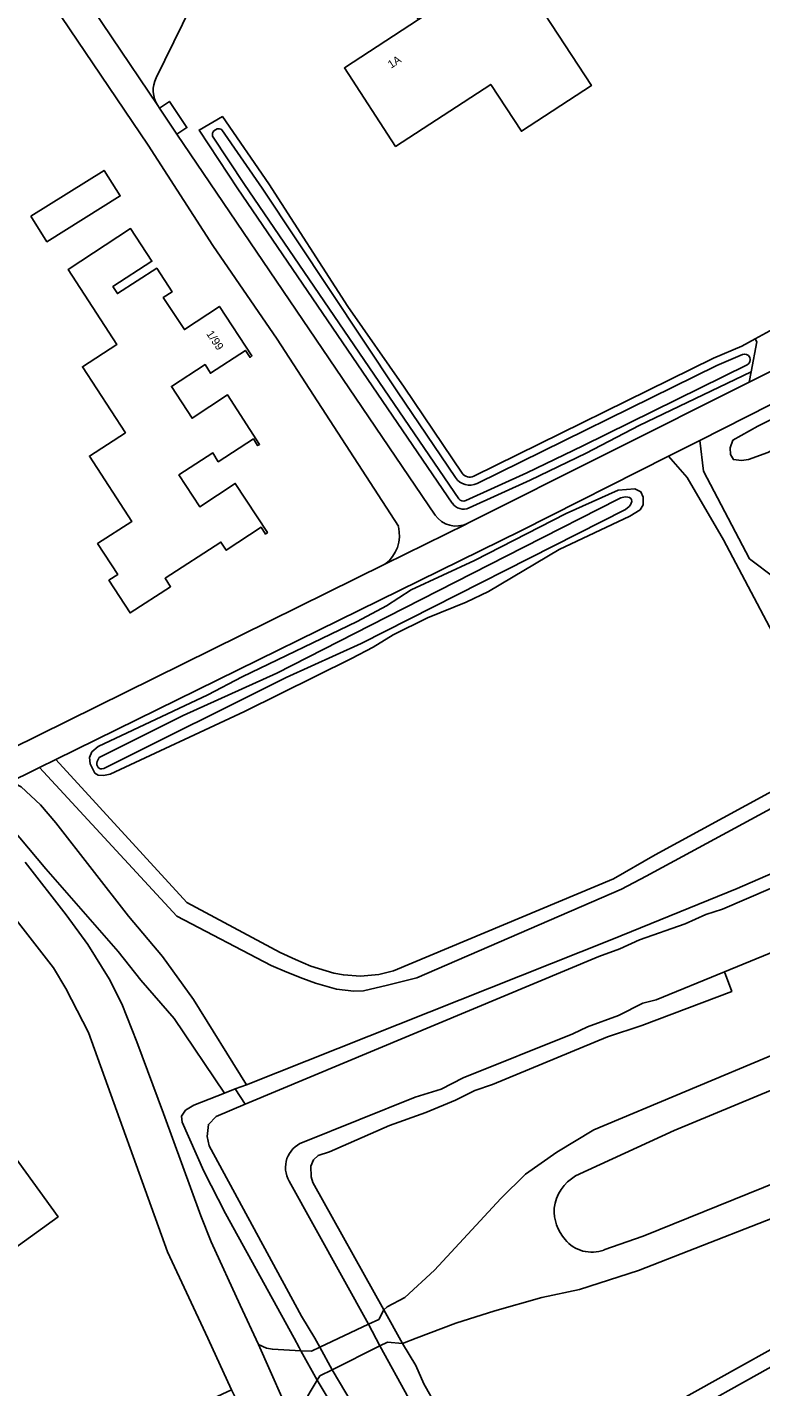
# Model space of a CAD drawing. Extents: x 162788 to 163838, y 385791 to 386523.
# Drawn here: x 163143.1 to 163234.7, y 386243.9 to 386413.8 of the extents above; entities that cross this region are included whole.
import ezdxf

# ---------------------------------------------------------------- set-up
doc = ezdxf.new("R2010")
doc.units = 0
for name, color, linetype in [('IMGEO_Dek', 7, 'Continuous'), ('IMGEO_Duiker', 7, 'Continuous'), ('IMGEO_Erf', 7, 'Continuous'), ('IMGEO_Gemengd_bos', 7, 'Continuous'), ('IMGEO_Groenvoorziening', 7, 'Continuous'), ('IMGEO_Oever', 7, 'Continuous'), ('IMGEO_Pand', 7, 'Continuous'), ('IMGEO_Pand_nummerreeks', 7, 'Continuous'), ('IMGEO_Pand_vergunning_verleend', 7, 'Continuous'), ('IMGEO_Rijbaan_lokaal_gesloten', 7, 'Continuous'), ('IMGEO_Voetpad_halfverhard', 7, 'Continuous'), ('IMGEO_Voetpad_open', 7, 'Continuous'), ('IMGEO_Waterloop', 7, 'Continuous'), ('IMGEO_Woonerf_open', 7, 'Continuous')]:
    doc.layers.add(name, color=color, linetype=linetype)

msp = doc.modelspace()

# ---------------------------------------------------------------- linework, layer by layer
at = {"layer": 'IMGEO_Dek'}
msp.add_lwpolyline([(163187.14, 386249.05), (163188.1, 386249.52), (163189.98, 386249.35), (163187.66, 386253.56), (163187.03, 386252.37), (163185.76, 386251.76), (163179.68, 386248.88), (163178.62, 386248.38), (163177.3, 386248.45), (163179.35, 386244.77), (163179.68, 386245.3), (163181.21, 386246.07)], close=True, dxfattribs=at)
at = {"layer": 'IMGEO_Duiker'}
msp.add_lwpolyline([(163170.35, 386279.25), (163169.11, 386281.15)], dxfattribs=at)
at = {"layer": 'IMGEO_Erf'}
for points in [[(163183.82, 386453.68), (163203.35, 386423.5), (163202.72, 386423.13), (163213.57, 386406.51), (163204.83, 386400.81), (163201, 386406.67), (163189.13, 386398.92), (163182.73, 386408.73), (163191.99, 386414.77), (163181.96, 386429.74), (163190.95, 386435.96), (163184.59, 386445.9)], [(163176.85, 386443.41), (163159.22, 386407.47)], [(163189.47, 386351.45), (163174.34, 386374.85), (163166.31, 386386.55), (163158.23, 386399.07), (163142.49, 386422.41)], [(163198.88, 386357.71), (163228.84, 386372.45), (163232.38, 386373.97), (163234.01, 386374.89), (163236.33, 386376.13), (163247.03, 386381.44), (163261.91, 386388.47), (163285.34, 386400.29), (163291.96, 386403.48), (163304.5, 386410.04)], [(163159.42, 386404.03), (163159.64, 386403.68), (163160.87, 386404.53), (163163.06, 386401.27), (163161.79, 386400.43), (163194.06, 386352.86)], [(163196.21, 386354.34), (163169.41, 386393.61), (163164.58, 386400.96), (163167.5, 386402.64), (163173.28, 386394.26), (163183.14, 386378.9), (163190.19, 386368.84), (163197.45, 386358.09)], [(163198.08, 386351.82), (163233.27, 386369.45), (163233.53, 386370.77), (163219.54, 386364.04), (163212.94, 386360.6), (163205.94, 386357.23), (163198.3, 386353.75)], [(163091.31, 386354.73), (163115.97, 386329.92), (163121.7, 386323.72), (163123.09, 386322.59), (163126.27, 386320.63), (163127.78, 386320.01), (163129.72, 386319.21), (163129.91, 386319.12), (163130.11, 386319.04), (163130.32, 386318.97), (163130.52, 386318.93), (163130.74, 386318.9), (163130.95, 386318.89), (163131.17, 386318.9), (163131.38, 386318.93), (163131.59, 386318.97), (163131.8, 386319.04), (163132, 386319.12), (163132.19, 386319.21), (163137.37, 386321.83), (163187.8, 386346.71)], [(163202.05, 386229.7), (163238.52, 386250), (163263.57, 386263.94), (163278.14, 386271.64), (163288.89, 386277.59), (163289.29, 386277.99), (163289.57, 386278.55), (163289.29, 386279.83), (163285.21, 386290.76), (163283.84, 386294.94), (163285.26, 386295.57), (163284.13, 386298.22), (163282.71, 386297.57), (163282.08, 386299.04), (163280.52, 386303.16), (163279.76, 386304.64), (163276.83, 386311.46)], [(163130.61, 386225.91), (163168.65, 386243.58), (163165.66, 386250), (163160.64, 386260.8), (163150.79, 386288.19), (163147.95, 386293.69), (163146.39, 386296.27), (163137.48, 386307.69)], [(163252.5, 386304.93), (163230.21, 386295.8), (163231.11, 386293.35), (163219.88, 386289.08), (163215.6, 386287.65), (163201.22, 386281.72), (163199.02, 386280.98), (163196.61, 386279.76), (163192.89, 386278.2), (163188.38, 386276.6), (163180.89, 386273.3), (163179.47, 386272.86), (163178.89, 386272.28), (163178.54, 386271.49), (163178.59, 386270.16), (163178.79, 386269.46), (163187.66, 386253.56), (163188.07, 386253.92), (163190.27, 386255.1), (163193.97, 386258.51), (163202.25, 386267.46), (163205.34, 386270.51), (163209.26, 386273.27), (163213.9, 386276.05), (163236.95, 386285.72)], [(163139.77, 386275.14), (163146.97, 386265.18), (163119.61, 386245.38)], [(163242.46, 386267.47), (163219.47, 386258.48), (163212.11, 386256.1), (163207.4, 386255.09), (163201.52, 386253.45), (163196.64, 386251.88), (163191.7, 386250), (163189.98, 386249.35), (163191.66, 386246.6), (163192.64, 386244.3), (163200.49, 386230.52)]]:
    msp.add_lwpolyline(points, dxfattribs=at)
msp.add_lwpolyline([(163151.91, 386349.29), (163156.19, 386352.07), (163150.89, 386360.23), (163155.38, 386363.14), (163150.02, 386371.39), (163154.3, 386374.16), (163148.22, 386383.52), (163156.04, 386388.64), (163158.69, 386384.56), (163153.82, 386381.4), (163154.38, 386380.52), (163159.29, 386383.69), (163161.21, 386380.74), (163160.11, 386380.03), (163162.75, 386376.04), (163167.13, 386378.92), (163171.18, 386372.74), (163170.95, 386372.55), (163170.37, 386373.43), (163166.01, 386370.57), (163165.33, 386371.66), (163161.12, 386368.93), (163163.7, 386364.96), (163168.14, 386367.86), (163172.15, 386361.69), (163171.9, 386361.54), (163171.36, 386362.38), (163166.98, 386359.52), (163166.31, 386360.63), (163162.07, 386357.88), (163164.66, 386353.89), (163169.1, 386356.82), (163173.12, 386350.66), (163172.89, 386350.49), (163172.32, 386351.34), (163167.97, 386348.46), (163167.31, 386349.49), (163160.34, 386344.96), (163161.02, 386343.91), (163155.97, 386340.63), (163153.32, 386344.72), (163154.42, 386345.44)], close=True, dxfattribs=at)
for centre, radius, start, end in [((163162.36, 386405.93), 3.5, 153.8321, 212.7602), ((163198.38, 386358.72), 1.13, 213.9935, 296.382), ((163197.6, 386355.28), 1.68, 214.2495, 294.4272), ((163185.11, 386350.32), 4.5, 306.6921, 14.4455), ((163196.67, 386354.64), 3.16, 214.3208, 296.6637)]:
    msp.add_arc(centre, radius, start, end, dxfattribs=at)
at = {"layer": 'IMGEO_Gemengd_bos'}
for points in [[(163251.31, 386374.37), (163244.77, 386371.12), (163227.11, 386362.18), (163227.57, 386358.35), (163233.34, 386347.39), (163236.53, 386344.99), (163240.87, 386344.48), (163246.3, 386346.08), (163265.57, 386354.14), (163258.98, 386369.88)], [(163249.73, 386367.6), (163239.39, 386362.73), (163235.63, 386360.67), (163233.19, 386359.79), (163232.32, 386359.69), (163231.31, 386359.79), (163230.93, 386360.43), (163230.89, 386361.27), (163231.25, 386362.21), (163234.35, 386363.97), (163242.51, 386368), (163251.65, 386372.2), (163251.93, 386372.33)], [(163245.56, 386321.36), (163220.43, 386307.74), (163217.35, 386306.13), (163191.76, 386295.05), (163188.1, 386294.14), (163185.1, 386293.41), (163183.89, 386293.36), (163181.73, 386293.63), (163179.14, 386294.37), (163177.56, 386294.94), (163175.56, 386295.74), (163173.59, 386296.58), (163161.79, 386302.75), (163144.67, 386321.31), (163140.19, 386319.11)], [(163142.36, 386318.89), (163144.8, 386316.64), (163146.68, 386314.42), (163155.79, 386302.74), (163160.03, 386297.72), (163163.89, 386292.32), (163170.49, 386281.68), (163216.12, 386299.84), (163231.77, 386306.19), (163236.27, 386308.14)], [(163142.88, 386309.51), (163148, 386302.92), (163150.68, 386299.19), (163153.35, 386294.91), (163154.95, 386291.78), (163156.81, 386287.04), (163160.14, 386278.08), (163164.81, 386265.29), (163166.11, 386262.07), (163169.72, 386254.16), (163171.99, 386249.22), (163173.01, 386248.79), (163173.75, 386248.64), (163177.3, 386248.45), (163177.07, 386248.86), (163176.45, 386250), (163167.9, 386265.59), (163165.18, 386270.87), (163162.48, 386277.01), (163162.4, 386277.75), (163162.9, 386278.49), (163163.94, 386279.15), (163167.75, 386280.62), (163161.49, 386289.96), (163157.29, 386294.73), (163154.47, 386298.31), (163145.44, 386308.65), (163140.02, 386315.11)]]:
    msp.add_lwpolyline(points, dxfattribs=at)
for points in [[(163223.2, 386360.2), (163204.76, 386350.87), (163146.68, 386322.3), (163163.05, 386304.46), (163174.71, 386298.21), (163176.62, 386297.32), (163178.56, 386296.51), (163181.4, 386295.62), (163182.61, 386295.4), (163184.73, 386295.24), (163187.04, 386295.46), (163188.87, 386295.91), (163216.32, 386307.39), (163221.54, 386310.39), (163244.17, 386322.73), (163244.86, 386324.42), (163239.28, 386332.37), (163230.09, 386349.78), (163225.52, 386357.53)], [(163209.54, 386348.55), (163200.74, 386343.3), (163197.94, 386341.96), (163193.12, 386340.02), (163188.82, 386337.91), (163186.33, 386336.35), (163183.63, 386334.93), (163170.27, 386328.3), (163153.46, 386320.5), (163152.64, 386320.3), (163151.98, 386320.36), (163151.58, 386320.62), (163151, 386321.78), (163150.92, 386322.58), (163151.2, 386323.26), (163151.98, 386323.94), (163165.69, 386330.39), (163169.95, 386332.64), (163184.33, 386339.55), (163188.01, 386341.51), (163191.08, 386343.52), (163198.98, 386347.2), (163210.42, 386353.07), (163216.94, 386355.98), (163219.02, 386356.12), (163219.76, 386355.76), (163220.05, 386355.08), (163220.04, 386354.14), (163219.65, 386353.5), (163218.39, 386352.7)]]:
    msp.add_lwpolyline(points, close=True, dxfattribs=at)
at = {"layer": 'IMGEO_Groenvoorziening'}
for points in [[(163238.51, 386281.93), (163236.46, 386281.19), (163223.91, 386275.96), (163211.61, 386270.29)], [(163215.15, 386261.04), (163220.05, 386262.77), (163240.72, 386271.13)], [(163182.41, 386239.63), (163179.69, 386244.16), (163179.35, 386244.77), (163178.47, 386243.33)]]:
    msp.add_lwpolyline(points, dxfattribs=at)
for centre, radius, start, end in [((163214.22, 386265.65), 5.32, 119.4185, 173.4513), ((163214.33, 386265.94), 5.4, 176.5722, 221.7042), ((163213.64, 386265.1), 4.34, 219.5286, 290.4148)]:
    msp.add_arc(centre, radius, start, end, dxfattribs=at)
at = {"layer": 'IMGEO_Oever'}
for points in [[(163197.45, 386358.09), (163190.19, 386368.84), (163183.14, 386378.9), (163173.28, 386394.26), (163167.5, 386402.64), (163164.58, 386400.96), (163169.41, 386393.61), (163196.21, 386354.34)], [(163166.44, 386400.88), (163166.84, 386401.11)], [(163167.43, 386400.97), (163172.45, 386393.71), (163189.37, 386368.27), (163196.62, 386357.53)], [(163197.04, 386354.9), (163170.24, 386394.17), (163166.28, 386400.2)], [(163198.3, 386353.75), (163205.94, 386357.23), (163212.94, 386360.6), (163219.54, 386364.04), (163233.53, 386370.77), (163234.25, 386374.48), (163234.01, 386374.89)], [(163234.01, 386374.89), (163232.38, 386373.97), (163228.84, 386372.45), (163198.88, 386357.71)], [(163233.01, 386371.63), (163212.49, 386361.5), (163205.52, 386358.14), (163197.88, 386354.66)], [(163199.32, 386356.81), (163229.26, 386371.54), (163232.43, 386372.9)], [(163201.42, 386227.1), (163242.44, 386250), (163262.13, 386260.88), (163269.34, 386264.69), (163291.27, 386277.25), (163291.53, 386278.53), (163291.33, 386279.8), (163290.03, 386283.66), (163289.41, 386284.9), (163286.87, 386291.58), (163285.47, 386295.67), (163284.47, 386298.38), (163278.52, 386313.1), (163278.21, 386313.61), (163277.03, 386314.34), (163275.95, 386314.7), (163274.89, 386314.47), (163271.39, 386312.98), (163272.19, 386310.89), (163274.55, 386311.97)], [(163276.83, 386311.46), (163279.76, 386304.64), (163280.52, 386303.16), (163282.08, 386299.04), (163282.71, 386297.57), (163284.13, 386298.22), (163285.26, 386295.57), (163283.84, 386294.94), (163285.21, 386290.76), (163289.29, 386279.83), (163289.57, 386278.55), (163289.29, 386277.99), (163288.89, 386277.59), (163278.14, 386271.64), (163263.57, 386263.94), (163238.52, 386250), (163202.05, 386229.7), (163201.46, 386229.64), (163200.89, 386229.9), (163200.49, 386230.52), (163192.64, 386244.3)], [(163184.51, 386240.51), (163181.21, 386246.07), (163179.68, 386248.88), (163179.02, 386250), (163177.39, 386252.77), (163165.86, 386274.05), (163165.6, 386275.21), (163165.76, 386276.73), (163166.7, 386277.73), (163170.35, 386279.25), (163214.5, 386297.72), (163217.14, 386298.68), (163219.6, 386299.78), (163225.3, 386301.79), (163227.87, 386302.95), (163229.95, 386303.61), (163242.23, 386308.92)], [(163236.27, 386308.14), (163231.77, 386306.19), (163216.12, 386299.84), (163170.49, 386281.68), (163169.11, 386281.15), (163167.75, 386280.62), (163163.94, 386279.15), (163162.9, 386278.49), (163162.4, 386277.75), (163162.48, 386277.01), (163165.18, 386270.87), (163167.9, 386265.59), (163176.45, 386250), (163177.07, 386248.86), (163177.3, 386248.45), (163179.35, 386244.77), (163179.69, 386244.16), (163182.41, 386239.63)], [(163192.64, 386244.3), (163191.66, 386246.6), (163189.98, 386249.35), (163187.66, 386253.56), (163178.79, 386269.46), (163178.59, 386270.16), (163178.54, 386271.49), (163178.89, 386272.28), (163179.47, 386272.86), (163180.89, 386273.3), (163188.38, 386276.6), (163192.89, 386278.2), (163196.61, 386279.76), (163199.02, 386280.98), (163201.22, 386281.72), (163215.6, 386287.65), (163219.88, 386289.08), (163231.11, 386293.35), (163230.21, 386295.8), (163221.65, 386292.3), (163220.02, 386291.86), (163216.98, 386290.34), (163213.1, 386288.91), (163211.26, 386288.03), (163197.57, 386282.54), (163194.83, 386281.12), (163191.59, 386280.13), (163177.49, 386274.48)], [(163175.83, 386269.65), (163185.76, 386251.76), (163187.14, 386249.05), (163190.78, 386242.48)]]:
    msp.add_lwpolyline(points, dxfattribs=at)
for points in [[(163200.74, 386343.3), (163209.54, 386348.55), (163218.39, 386352.7), (163219.65, 386353.5), (163220.04, 386354.14), (163220.05, 386355.08), (163219.76, 386355.76), (163219.02, 386356.12), (163216.94, 386355.98), (163210.42, 386353.07), (163198.98, 386347.2), (163191.08, 386343.52), (163188.01, 386341.51), (163184.33, 386339.55), (163169.95, 386332.64), (163165.69, 386330.39), (163151.98, 386323.94), (163151.2, 386323.26), (163150.92, 386322.58), (163151, 386321.78), (163151.58, 386320.62), (163151.98, 386320.36), (163152.64, 386320.3), (163153.46, 386320.5), (163170.27, 386328.3), (163183.63, 386334.93), (163186.33, 386336.35), (163188.82, 386337.91), (163193.12, 386340.02), (163197.94, 386341.96)], [(163152.68, 386321.18), (163152.42, 386321.13), (163152.22, 386321.15), (163151.98, 386321.33), (163151.83, 386321.67), (163151.81, 386321.84), (163151.86, 386322.08), (163152.1, 386322.56), (163162.61, 386327.82), (163174.3, 386333.11), (163185.93, 386339.04), (163205.14, 386348.84), (163216.9, 386354.84), (163217.27, 386355.02), (163217.81, 386355.14), (163218.12, 386355.1), (163218.33, 386355.03), (163218.5, 386354.91), (163218.57, 386354.81), (163218.61, 386354.57), (163218.46, 386354.15), (163218.28, 386353.91), (163217.85, 386353.55), (163184.83, 386336.8), (163175.44, 386332.58)]]:
    msp.add_lwpolyline(points, close=True, dxfattribs=at)
for centre, radius, start, end in [((163166.99, 386400.39), 0.738, 138.1945, 195.194), ((163166.99, 386400.39), 0.735, 52.6278, 101.9294), ((163232.71, 386372.26), 0.7, 295.6804, 113.2007), ((163198.38, 386358.72), 1.13, 213.9935, 296.382), ((163198.38, 386358.72), 2.13, 213.9686, 296.2003), ((163197.6, 386355.28), 0.681, 214.3174, 294.2772), ((163197.6, 386355.28), 1.68, 214.2495, 294.4272), ((163178.75, 386271.35), 3.37, 111.8018, 210.2063)]:
    msp.add_arc(centre, radius, start, end, dxfattribs=at)
at = {"layer": 'IMGEO_Pand'}
for points in [[(163191.99, 386414.77), (163182.73, 386408.73), (163189.13, 386398.92), (163201, 386406.67), (163204.83, 386400.81), (163213.57, 386406.51), (163202.72, 386423.13), (163193.99, 386417.37), (163194.58, 386416.46)], [(163155.97, 386340.63), (163161.02, 386343.91), (163160.34, 386344.96), (163167.31, 386349.49), (163167.97, 386348.46), (163172.32, 386351.34), (163172.89, 386350.49), (163173.12, 386350.66), (163169.1, 386356.82), (163164.66, 386353.89), (163162.07, 386357.88), (163166.31, 386360.63), (163166.98, 386359.52), (163171.36, 386362.38), (163171.9, 386361.54), (163172.15, 386361.69), (163168.14, 386367.86), (163163.7, 386364.96), (163161.12, 386368.93), (163165.33, 386371.66), (163166.01, 386370.57), (163170.37, 386373.43), (163170.95, 386372.55), (163171.18, 386372.74), (163167.13, 386378.92), (163162.75, 386376.04), (163160.11, 386380.03), (163161.21, 386380.74), (163159.29, 386383.69), (163154.38, 386380.52), (163153.82, 386381.4), (163158.69, 386384.56), (163156.04, 386388.64), (163148.22, 386383.52), (163154.3, 386374.16), (163150.02, 386371.39), (163155.38, 386363.14), (163150.89, 386360.23), (163156.19, 386352.07), (163151.91, 386349.29), (163154.42, 386345.44), (163153.32, 386344.72)]]:
    msp.add_lwpolyline(points, close=True, dxfattribs=at)
msp.add_lwpolyline([(163119.61, 386245.38), (163146.97, 386265.18), (163139.77, 386275.14)], dxfattribs=at)
at = {"layer": 'IMGEO_Pand_vergunning_verleend'}
msp.add_lwpolyline([(163143.58, 386390.2), (163152.73, 386395.92), (163154.73, 386392.72), (163145.58, 386387)], close=True, dxfattribs=at)
at = {"layer": 'IMGEO_Rijbaan_lokaal_gesloten'}
for points in [[(163187.14, 386249.05), (163188.1, 386249.52), (163189.98, 386249.35), (163187.66, 386253.56), (163187.03, 386252.37), (163185.76, 386251.76), (163179.68, 386248.88), (163178.62, 386248.38), (163177.3, 386248.45), (163179.35, 386244.77), (163179.68, 386245.3), (163181.21, 386246.07)], [(163177.3, 386248.45), (163173.75, 386248.64), (163173.01, 386248.79), (163171.99, 386249.22), (163176.56, 386238.97), (163176.88, 386240.52), (163178.47, 386243.33), (163179.35, 386244.77)]]:
    msp.add_lwpolyline(points, close=True, dxfattribs=at)
at = {"layer": 'IMGEO_Voetpad_halfverhard'}
for points in [[(163236.53, 386344.99), (163233.34, 386347.39), (163227.57, 386358.35), (163227.11, 386362.18), (163223.2, 386360.2), (163225.52, 386357.53), (163230.09, 386349.78), (163239.28, 386332.37)], [(163244.17, 386322.73), (163221.54, 386310.39), (163216.32, 386307.39), (163188.87, 386295.91), (163187.04, 386295.46), (163184.73, 386295.24), (163182.61, 386295.4), (163181.4, 386295.62), (163178.56, 386296.51), (163176.62, 386297.32), (163174.71, 386298.21), (163163.05, 386304.46), (163146.68, 386322.3), (163144.67, 386321.31), (163161.79, 386302.75), (163173.59, 386296.58), (163175.56, 386295.74), (163177.56, 386294.94), (163179.14, 386294.37), (163181.73, 386293.63), (163183.89, 386293.36), (163185.1, 386293.41), (163188.1, 386294.14), (163191.76, 386295.05), (163217.35, 386306.13), (163220.43, 386307.74), (163245.56, 386321.36)]]:
    msp.add_lwpolyline(points, dxfattribs=at)
at = {"layer": 'IMGEO_Voetpad_open'}
for points in [[(163159.22, 386407.47), (163176.85, 386443.41)], [(163147.85, 386421.24), (163159.42, 386404.03)], [(163236.95, 386285.72), (163213.9, 386276.05), (163209.26, 386273.27), (163205.34, 386270.51), (163202.25, 386267.46), (163193.97, 386258.51), (163190.27, 386255.1), (163188.07, 386253.92), (163187.66, 386253.56), (163189.98, 386249.35), (163191.7, 386250), (163196.64, 386251.88), (163201.52, 386253.45), (163207.4, 386255.09), (163212.11, 386256.1), (163219.47, 386258.48), (163242.46, 386267.47)], [(163211.61, 386270.29), (163223.91, 386275.96), (163236.46, 386281.19), (163238.51, 386281.93)], [(163242.62, 386272.01), (163240.72, 386271.13), (163220.05, 386262.77), (163215.15, 386261.04)]]:
    msp.add_lwpolyline(points, dxfattribs=at)
for points in [[(163161.79, 386400.43), (163163.06, 386401.27), (163160.87, 386404.53), (163159.64, 386403.68)], [(163239.27, 386373.67), (163236.92, 386375.11), (163236.33, 386376.13), (163234.01, 386374.89), (163234.25, 386374.48), (163233.53, 386370.77), (163233.27, 386369.45), (163240.37, 386373.01)]]:
    msp.add_lwpolyline(points, close=True, dxfattribs=at)
for centre, radius, start, end in [((163162.36, 386405.93), 3.5, 153.8321, 212.7602), ((163214.22, 386265.65), 5.32, 119.4185, 173.4513), ((163214.33, 386265.94), 5.4, 176.5722, 221.7042), ((163213.64, 386265.1), 4.34, 219.5286, 290.4148)]:
    msp.add_arc(centre, radius, start, end, dxfattribs=at)
at = {"layer": 'IMGEO_Waterloop'}
for points in [[(163166.84, 386401.11), (163166.44, 386400.88)], [(163196.62, 386357.53), (163189.37, 386368.27), (163172.45, 386393.71), (163167.43, 386400.97)], [(163166.28, 386400.2), (163170.24, 386394.17), (163197.04, 386354.9)], [(163197.88, 386354.66), (163205.52, 386358.14), (163212.49, 386361.5), (163233.01, 386371.63)], [(163232.43, 386372.9), (163229.26, 386371.54), (163199.32, 386356.81)], [(163251.93, 386372.33), (163251.65, 386372.2), (163242.51, 386368), (163234.35, 386363.97), (163231.25, 386362.21), (163230.89, 386361.27), (163230.93, 386360.43), (163231.31, 386359.79), (163232.32, 386359.69), (163233.19, 386359.79), (163235.63, 386360.67), (163239.39, 386362.73), (163249.73, 386367.6)], [(163242.23, 386308.92), (163229.95, 386303.61), (163227.87, 386302.95), (163225.3, 386301.79), (163219.6, 386299.78), (163217.14, 386298.68), (163214.5, 386297.72), (163170.35, 386279.25), (163166.7, 386277.73), (163165.76, 386276.73), (163165.6, 386275.21), (163165.86, 386274.05), (163177.39, 386252.77), (163179.02, 386250), (163179.68, 386248.88), (163181.21, 386246.07), (163184.51, 386240.51)], [(163177.49, 386274.48), (163191.59, 386280.13), (163194.83, 386281.12), (163197.57, 386282.54), (163211.26, 386288.03), (163213.1, 386288.91), (163216.98, 386290.34), (163220.02, 386291.86), (163221.65, 386292.3), (163230.21, 386295.8), (163252.5, 386304.93)], [(163269.34, 386264.69), (163262.13, 386260.88), (163242.44, 386250), (163201.42, 386227.1), (163200.88, 386226.92), (163199.7, 386227.18), (163199.28, 386227.57), (163195.42, 386234.62), (163190.78, 386242.48), (163187.14, 386249.05), (163185.76, 386251.76), (163175.83, 386269.65)]]:
    msp.add_lwpolyline(points, dxfattribs=at)
for points in [[(163217.85, 386353.55), (163218.28, 386353.91), (163218.46, 386354.15), (163218.61, 386354.57), (163218.57, 386354.81), (163218.5, 386354.91), (163218.33, 386355.03), (163218.12, 386355.1), (163217.81, 386355.14), (163217.27, 386355.02), (163216.9, 386354.84), (163205.14, 386348.84), (163185.93, 386339.04), (163174.3, 386333.11), (163162.61, 386327.82), (163152.1, 386322.56), (163151.86, 386322.08), (163151.81, 386321.84), (163151.83, 386321.67), (163151.98, 386321.33), (163152.22, 386321.15), (163152.42, 386321.13), (163152.68, 386321.18), (163175.44, 386332.58), (163184.83, 386336.8)], [(163169.11, 386281.15), (163170.49, 386281.68), (163163.89, 386292.32), (163160.03, 386297.72), (163155.79, 386302.74), (163146.68, 386314.42), (163144.8, 386316.64), (163142.36, 386318.89), (163141.64, 386319.29), (163140.18, 386318.76), (163139.8, 386318.11), (163139.62, 386316.27), (163140.02, 386315.11), (163145.44, 386308.65), (163154.47, 386298.31), (163157.29, 386294.73), (163161.49, 386289.96), (163167.75, 386280.62)]]:
    msp.add_lwpolyline(points, close=True, dxfattribs=at)
for centre, radius, start, end in [((163166.99, 386400.39), 0.738, 138.1945, 195.194), ((163166.99, 386400.39), 0.735, 52.6278, 101.9294), ((163232.71, 386372.26), 0.7, 295.6804, 113.2007), ((163198.38, 386358.72), 2.13, 213.9686, 296.2003), ((163197.6, 386355.28), 0.681, 214.3174, 294.2772), ((163178.75, 386271.35), 3.37, 111.8018, 210.2063)]:
    msp.add_arc(centre, radius, start, end, dxfattribs=at)
at = {"layer": 'IMGEO_Woonerf_open'}
for points in [[(163161.79, 386400.43), (163159.64, 386403.68), (163159.42, 386404.03), (163147.85, 386421.24), (163145.04, 386425.84)], [(163142.49, 386422.41), (163158.23, 386399.07), (163166.31, 386386.55), (163174.34, 386374.85), (163189.47, 386351.45)], [(163194.06, 386352.86), (163161.79, 386400.43)], [(163140.19, 386319.11), (163144.67, 386321.31), (163146.68, 386322.3), (163204.76, 386350.87), (163223.2, 386360.2), (163227.11, 386362.18), (163244.77, 386371.12), (163243.18, 386374.41), (163240.37, 386373.01), (163233.27, 386369.45), (163198.08, 386351.82), (163197.93, 386351.71), (163187.8, 386346.71), (163137.37, 386321.83)], [(163187.8, 386346.71), (163197.93, 386351.71), (163198.08, 386351.82)], [(163171.99, 386249.22), (163169.72, 386254.16), (163166.11, 386262.07), (163164.81, 386265.29), (163160.14, 386278.08), (163156.81, 386287.04), (163154.95, 386291.78), (163153.35, 386294.91), (163150.68, 386299.19), (163148, 386302.92), (163142.88, 386309.51)], [(163137.48, 386307.69), (163146.39, 386296.27), (163147.95, 386293.69), (163150.79, 386288.19), (163160.64, 386260.8), (163165.66, 386250), (163168.65, 386243.58), (163169.67, 386241.49), (163171.11, 386238.28), (163177.05, 386225.08), (163177.79, 386223.44), (163180.25, 386217.97), (163183.27, 386211.27), (163184.32, 386208.97), (163185.2, 386207.04)], [(163176.56, 386238.97), (163171.99, 386249.22)]]:
    msp.add_lwpolyline(points, dxfattribs=at)
for centre, radius, start, end in [((163185.11, 386350.32), 4.5, 306.6921, 14.4455), ((163196.67, 386354.64), 3.16, 214.3208, 296.6637)]:
    msp.add_arc(centre, radius, start, end, dxfattribs=at)

# ---------------------------------------------------------------- texts
at = {"layer": 'IMGEO_Pand_nummerreeks'}
for s, rotation, p in [('1A', 33.137, (163188.56, 386408.61)), ('1/99', 303.9202, (163165.44, 386375.5))]:
    msp.add_text(s, height=1, rotation=rotation, dxfattribs=at).set_placement(p)

doc.saveas('drawing.dxf')
